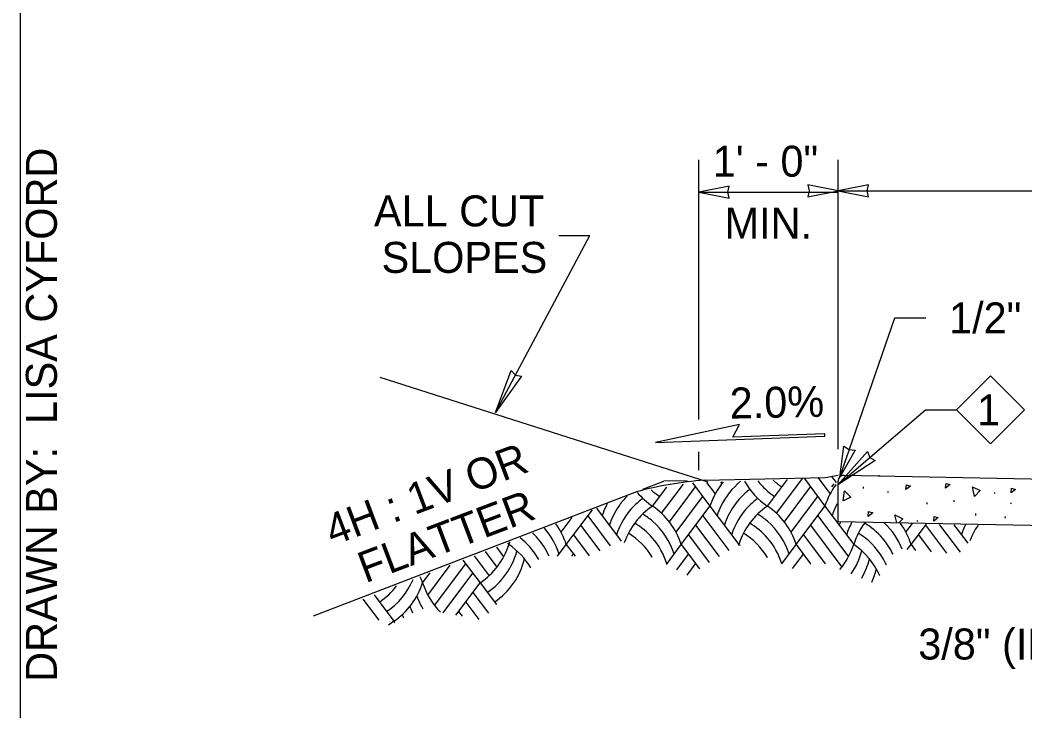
# Model space of a CAD drawing. Extents: x 99862 to 103151, y 100000 to 102076.
# Drawn here: x 99862 to 100381, y 100967 to 101323 of the extents above; entities that cross this region are included whole.
import ezdxf

# ---------------------------------------------------------------- set-up
doc = ezdxf.new("R2010")
doc.units = 0
for name, color, linetype in [('Level 1', 7, 'Continuous'), ('Level 13', 7, 'Continuous'), ('Level 15', 7, 'Continuous'), ('Level 20', 7, 'Continuous'), ('Level 28', 7, 'Continuous'), ('Level 34', 7, 'Continuous'), ('Level 6', 7, 'Continuous'), ('Level 62', 7, 'Continuous')]:
    doc.layers.add(name, color=color, linetype=linetype)

msp = doc.modelspace()

# ---------------------------------------------------------------- linework, layer by layer
at = {"layer": 'Level 1'}
msp.add_lwpolyline([(99862, 99999.5), (103151, 99999.5), (103151, 102075.5), (99862, 102075.5)], close=True, dxfattribs=at)
at = {"layer": 'Level 13'}
for p, q in [((100305.73, 101088.23), (100305.82, 101088.16)), ((100306.04, 101088.23), (100306.22, 101088.09)), ((100297.74, 101081.47), (100297.81, 101082.34)), ((100310.12, 101079.93), (100310.64, 101079.55)), ((100365.2, 101079.65), (100365.56, 101078.92)), ((100330.67, 101073.33), (100330.73, 101074.2)), ((100344.6, 101074.52), (100344.66, 101075.39)), ((100373.66, 101074.13), (100374.17, 101073.76)), ((100355.71, 101067.6), (100355.77, 101068.48)), ((100325.23, 101065.1), (100325.58, 101064.38)), ((100370.98, 101066.16), (100371.04, 101067.03))]:
    msp.add_line(p, q, dxfattribs=at)
for points in [[(100319.67, 101080.95), (100319.91, 101083.4), (100322.04, 101082.75), (100319.67, 101080.95)], [(100340.13, 101081.64), (100340.38, 101084.09), (100342.5, 101083.45), (100340.13, 101081.64)], [(100287.3, 101075.12), (100288, 101080.19), (100291.18, 101076.91), (100287.38, 101075.15)], [(100355.06, 101077.35), (100353.99, 101082.36), (100358.1, 101080.36), (100355.13, 101077.41)], [(100374, 101079.17), (100374.24, 101081.62), (100376.36, 101080.98), (100374, 101079.17)], [(100300.16, 101067.09), (100300.4, 101069.54), (100302.53, 101068.9), (100300.16, 101067.09)], [(100314.9, 101063.68), (100314.02, 101067.81), (100318.13, 101065.81), (100315.96, 101063.66)], [(100334.02, 101064.62), (100334.27, 101067.07), (100336.39, 101066.43), (100334.02, 101064.62)]]:
    msp.add_lwpolyline(points, dxfattribs=at)
at = {"layer": 'Level 15'}
for p, q in [((100212.64, 101117.17), (100212.64, 101251.17)), ((100284.64, 101101.73), (100284.64, 101251.17)), ((100212.64, 101234.46), (100284.64, 101234.46)), ((100284.64, 101235.17), (100715.89, 101235.17)), ((100107.64, 101120.76), (100156.3, 101212.09)), ((100140.3, 101212.09), (100156.3, 101212.09)), ((100285.54, 101087.37), (100313.97, 101169.56)), ((100313.97, 101169.56), (100329.97, 101169.56)), ((100284.44, 101083.42), (100329.75, 101122.02)), ((100329.75, 101122.02), (100345.75, 101122.02)), ((100212.64, 101090.9), (100212.64, 101100.37)), ((100183.77, 101081.04), (100194.66, 101085.23)), ((100206.66, 101085.47), (100194.66, 101085.23))]:
    msp.add_line(p, q, dxfattribs=at)
for points in [[(100212.64, 101234.46), (100228.37, 101231.38), (100227.64, 101234.46), (100228.37, 101237.54)], [(100284.64, 101235.17), (100268.92, 101238.25), (100269.64, 101235.17), (100268.92, 101232.08)], [(100284.64, 101235.17), (100300.37, 101232.08), (100299.64, 101235.17), (100300.37, 101238.25)], [(100107.64, 101120.76), (100115.74, 101142.31), (100117.88, 101139.98), (100121.01, 101139.51)], [(100284.44, 101083.42), (100299.88, 101100.5), (100301.01, 101097.54), (100303.75, 101095.95)], [(100285.54, 101087.37), (100287.66, 101103.25), (100290.35, 101101.58), (100293.5, 101101.28)]]:
    msp.add_lwpolyline(points, close=True, dxfattribs=at)
at = {"layer": 'Level 20'}
for points in [[(100363.31, 101139.57), (100380.86, 101122.02), (100363.31, 101104.47), (100345.75, 101122.02)], [(100277.72, 101109.68), (100230.26, 101107.96), (100233.77, 101114.57), (100190.32, 101105.28), (100277.77, 101108.44)]]:
    msp.add_lwpolyline(points, close=True, dxfattribs=at)
at = {"layer": 'Level 28'}
for p, q in [((100217.57, 101084.73), (100048.01, 101138.81)), ((100277.88, 101087.19), (100284.64, 101088.29)), ((100215.65, 101085.72), (100277.88, 101087.19)), ((100180.43, 101079.76), (100013.48, 101015.61))]:
    msp.add_line(p, q, dxfattribs=at)
msp.add_arc((100228.98, 100900), 186.2, 94.1041, 105.1145, dxfattribs=at)
at = {"layer": 'Level 34'}
for p, q in [((100196.16, 101072.35), (100204.73, 101083.77)), ((100209.43, 101084.36), (100218.44, 101072.35)), ((100216.67, 101084.6), (100221.11, 101078.68)), ((100223.92, 101084.84), (100224.56, 101083.99)), ((100248.14, 101072.35), (100258.49, 101086.16)), ((100255.56, 101072.35), (100266.3, 101086.67)), ((100267.06, 101086.72), (100277.83, 101072.35)), ((100274.13, 101087.18), (100280.51, 101078.68)), ((100281.21, 101087.65), (100283.56, 101084.51)), ((100281.34, 101082.27), (100282.6, 101083.95)), ((100188.74, 101072.35), (100196.13, 101082.21)), ((100203.59, 101072.35), (100211.01, 101082.25)), ((100262.99, 101072.35), (100270.41, 101082.25)), ((100211.01, 101072.35), (100214.73, 101077.3)), ((100270.41, 101072.35), (100274.12, 101077.3)), ((100144.19, 101052.55), (100157.68, 101070.53)), ((100155.33, 101067.4), (100166.95, 101051.9)), ((100159.79, 101071.35), (100172.61, 101054.26)), ((100193.39, 101068.65), (100196.16, 101072.35)), ((100197.47, 101064.19), (100203.59, 101072.35)), ((100200.91, 101058.88), (100211.01, 101072.35)), ((100203.59, 101052.55), (100218.44, 101072.35)), ((100214.73, 101067.4), (100228.21, 101049.43)), ((100218.44, 101072.35), (100233.29, 101052.55)), ((100252.79, 101068.65), (100255.56, 101072.35)), ((100256.87, 101064.19), (100262.99, 101072.35)), ((100260.31, 101058.88), (100270.41, 101072.35)), ((100262.99, 101052.55), (100277.83, 101072.35)), ((100274.12, 101067.4), (100290.01, 101046.22)), ((100277.83, 101072.35), (100292.68, 101052.55)), ((100141.52, 101058.88), (100147.19, 101066.44)), ((100151.62, 101062.45), (100161.47, 101049.32)), ((100211.01, 101062.45), (100223.13, 101046.3)), ((100270.41, 101062.45), (100286.57, 101040.91)), ((100319.71, 101058.88), (100323.03, 101063.31)), ((100322.38, 101052.55), (100330.32, 101063.13)), ((100329.81, 101062.45), (100340.64, 101048.01)), ((100336.84, 101062.96), (100347.63, 101048.58)), ((100344.41, 101062.77), (100351.61, 101053.17)), ((100147.91, 101057.5), (100155.98, 101046.73)), ((100207.3, 101057.5), (100218.05, 101043.17)), ((100266.7, 101057.5), (100277.94, 101042.51)), ((100326.09, 101057.5), (100332.65, 101048.75)), ((100113.82, 101053.45), (100114.5, 101052.55)), ((100139.62, 101046.45), (100144.19, 101052.55)), ((100144.19, 101052.55), (100148.77, 101046.45)), ((100195.89, 101042.28), (100203.59, 101052.55)), ((100203.59, 101052.55), (100212.97, 101040.05)), ((100255.52, 101042.6), (100262.99, 101052.55)), ((100262.99, 101052.55), (100270.45, 101042.6)), ((100320.4, 101049.9), (100322.38, 101052.55)), ((100322.38, 101052.55), (100324.67, 101049.5)), ((100096.58, 101046.74), (100104.3, 101036.44)), ((100102.32, 101048.98), (100108.38, 101040.91)), ((100108.07, 101051.22), (100111.82, 101046.22)), ((100147.04, 101046.45), (100147.91, 101047.6)), ((100201.25, 101039.53), (100207.3, 101047.6)), ((100261.11, 101040.16), (100266.7, 101047.6)), ((100072.62, 101026.42), (100084.28, 101041.95)), ((100076.07, 101021.11), (100092.22, 101042.65)), ((100090.83, 101044.51), (100099.65, 101032.75)), ((100206.61, 101036.77), (100211.01, 101042.65)), ((100270.27, 101042.46), (100270.41, 101042.65)), ((100069.95, 101032.75), (100073.79, 101037.87)), ((100080.64, 101017.31), (100095.93, 101037.7)), ((100087.15, 101016.09), (100099.65, 101032.75)), ((100099.65, 101032.75), (100108.06, 101021.54)), ((100044.86, 101026.61), (100055.1, 101012.95)), ((100095.93, 101027.8), (100103.93, 101017.14)), ((100039.11, 101024.37), (100047.32, 101013.42)), ((100092.22, 101022.85), (100098.96, 101013.87)), ((100088.51, 101017.9), (100090.32, 101015.49))]:
    msp.add_line(p, q, dxfattribs=at)
for centre, start, end in [((100254.25, 101060.96), 140.4553, 162.3566), ((100257.96, 101056.01), 129.077, 154.2266), ((100269.1, 101103.54), 209.1264, 236.0964), ((100272.81, 101108.49), 217.7679, 228.9599), ((100276.52, 101113.44), 227.4889, 236.0964), ((100313.64, 101060.96), 143.0547, 162.3566), ((100209.7, 101103.54), 219.9022, 236.0964), ((100213.41, 101108.49), 227.5931, 228.9599), ((100213.41, 101108.49), 228.9599, 236.0964), ((100261.67, 101051.06), 127.1006, 145.4911), ((100272.81, 101108.49), 228.9599, 236.0964), ((100198.56, 101056.01), 152.2678, 154.2266), ((100202.28, 101051.06), 135.3023, 145.4911), ((100205.99, 101046.11), 126.331, 135.7128), ((100265.39, 101046.11), 126.331, 135.7128), ((100317.36, 101056.01), 152.1097, 154.2266), ((100198.56, 101056.01), 154.2265, 162.3566), ((100202.28, 101051.06), 145.491, 162.3566), ((100205.99, 101046.11), 135.7127, 162.3566), ((100209.7, 101041.16), 123.9036, 160.9173), ((100164.07, 101036.21), 48.9597, 58.5465), ((100167.78, 101041.16), 17.6434, 56.0963), ((100257.96, 101056.01), 154.2265, 162.3566), ((100261.67, 101051.06), 145.491, 162.3566), ((100265.39, 101046.11), 135.7127, 162.3566), ((100269.1, 101041.16), 123.9036, 162.3566), ((100223.46, 101036.21), 48.9597, 58.5465), ((100227.18, 101041.16), 17.6434, 56.0963), ((100317.36, 101056.01), 154.2265, 162.3566), ((100108.38, 101041.16), 17.6434, 35.8899), ((100160.36, 101031.26), 40.9413, 59.3021), ((100164.07, 101036.21), 17.6434, 48.9597), ((100219.75, 101031.26), 40.9413, 59.3021), ((100223.46, 101036.21), 17.6434, 48.9597), ((100321.07, 101051.06), 159.4391, 162.3566), ((100324.78, 101046.11), 151.3843, 162.3566), ((100328.49, 101041.16), 142.6953, 162.3566), ((100279.15, 101031.26), 40.9413, 59.3021), ((100282.86, 101036.21), 21.7759, 46.9781), ((100286.57, 101041.16), 17.6434, 36.4242), ((100380.46, 101051.06), 161.8541, 162.3566), ((100384.18, 101046.11), 153.9386, 162.3566), ((100387.89, 101041.16), 145.4824, 159.224), ((100338.54, 101031.26), 55.9227, 55.9244), ((100100.96, 101031.26), 40.9413, 46.4994), ((100104.67, 101036.21), 17.6434, 41.1054), ((100156.64, 101026.31), 31.6207, 58.4874), ((100216.04, 101026.31), 31.3316, 58.4874), ((100275.44, 101026.31), 31.3316, 58.4874), ((100078.69, 101063.94), 303.9036, 342.3566), ((100150.31, 101041.16), 160.1891, 162.3566), ((100093.54, 101021.36), 30.6224, 56.0964), ((100097.25, 101026.31), 31.3316, 52.1443), ((100100.96, 101031.26), 23.8349, 40.9414), ((100160.35, 101031.26), 17.6434, 40.9414), ((100197.48, 101063.94), 342.0481, 342.3566), ((100212.33, 101021.36), 54.4986, 56.0964), ((100219.75, 101031.26), 17.6434, 40.9414), ((100256.87, 101063.94), 319.6071, 342.3566), ((100271.72, 101021.36), 23.5386, 56.0964), ((100279.15, 101031.26), 25.6938, 40.9414), ((100082.4, 101058.99), 303.9036, 345.0113), ((100260.59, 101058.99), 324.8216, 345.0113), ((100086.11, 101054.04), 303.9036, 346.3199), ((100097.25, 101026.31), 29.5335, 31.3317), ((100216.04, 101026.31), 31.2901, 31.3317), ((100264.3, 101054.04), 329.9199, 346.3199), ((100275.43, 101026.31), 24.6223, 31.3317), ((100037.85, 101026.31), 17.6434, 17.8173), ((100268.01, 101049.09), 334.9477, 345.7713), ((100026.71, 101054.04), 303.9036, 322.4704), ((100030.43, 101049.09), 303.9036, 337.1009), ((100034.14, 101044.14), 303.9036, 342.3566), ((100034.14, 101021.36), 17.6434, 22.7998), ((100105.76, 101044.14), 197.6435, 224.9733), ((100102.05, 101039.19), 200.8778, 211.332), ((100094.62, 101029.29), 200.2432, 202.9094), ((100098.33, 101034.24), 201.4344, 206.7249), ((100102.05, 101039.19), 211.3319, 212.019), ((100076.06, 100981.76), 123.9036, 129.3064), ((100090.91, 101024.34), 197.6434, 199.0649)]:
    msp.add_arc(centre, 37.58, start, end, dxfattribs=at)
at = {"layer": 'Level 6'}
for p, q in [((100711.45, 101079.75), (100287.7, 101088.23)), ((100284.64, 101064.29), (100284.64, 101085.23)), ((100714.39, 101055.69), (100284.64, 101064.29))]:
    msp.add_line(p, q, dxfattribs=at)
msp.add_arc((100287.64, 101085.23), 3, 88.8542, 180, dxfattribs=at)

# ---------------------------------------------------------------- texts
at = {"layer": 'Level 20'}
for s, p in [('1\' - 0"', (100219.85, 101242.46)), ('ALL CUT', (100044.84, 101216.8)), ('MIN.', (100226.01, 101210.46)), ('SLOPES', (100048.75, 101192.8)), ('1/2" (IN) R. (TYP.)', (100341.97, 101161.56)), ('1', (100356.44, 101114.02)), ('3/8" (IN) PREMOLDED', (100326.05, 100993.16))]:
    msp.add_text(s, height=16, dxfattribs=at).set_placement(p)
for s, rotation, p in [('2.0%', 1.1458, (100228.78, 101117.52)), ('4H : 1V OR ', 20.6943, (100023.47, 101051.74)), ('FLATTER', 20.6943, (100040.42, 101032.49))]:
    msp.add_text(s, height=16, rotation=rotation, dxfattribs=at).set_placement(p)
at = {"layer": 'Level 62'}
msp.add_text('DRAWN BY:  LISA CYFORD', height=16, rotation=90, dxfattribs=at).set_placement((99881, 100981.64))

doc.saveas('drawing.dxf')
